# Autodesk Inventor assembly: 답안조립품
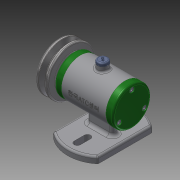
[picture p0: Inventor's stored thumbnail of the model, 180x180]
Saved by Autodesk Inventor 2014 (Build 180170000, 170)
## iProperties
Created: 2017-12
Part Number: 답안조립품
Document SubType Name: Assembly
Designer: 거성
Author: 거성
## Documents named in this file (14)
- C:\Users\거성\Desktop\471208V1027\답안조립품.iam
- C:\Users\거성\Desktop\471208V1027\본체.ipt
- C:\Users\거성\Desktop\471208V1027\앞커버.ipt
- C:\Users\거성\Desktop\471208V1027\오일 실 15 25 7.ipt
- C:\Users\거성\Desktop\471208V1027\베어링 15 x 32 x 9.ipt
- C:\Users\거성\Desktop\471208V1027\축.ipt
- C:\Users\거성\Desktop\471208V1027\뒤커버.ipt
- C:\Users\거성\Desktop\471208V1027\볼트 M4 x 12.ipt
- C:\Users\거성\Desktop\471208V1027\고무캡.ipt
- C:\Users\거성\Desktop\471208V1027\키 3 x 3 x 12.ipt
- C:\Users\거성\Desktop\471208V1027\V벨트풀리.ipt
- C:\Users\거성\Desktop\471208V1027\와셔 8x17.ipt
- C:\Users\거성\Desktop\471208V1027\스프링와셔 8.ipt
- C:\Users\거성\Desktop\471208V1027\너트 M 8.ipt
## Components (2 placed, 2 different names)
1. 고무캡:1
2. V벨트풀리:1
